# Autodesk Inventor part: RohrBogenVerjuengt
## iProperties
Shininess: 64.0
Length Units: 11269
Angle Units: 11279
Time Units: 11290
Mass Units: 11283
Length Display Precision: 5
Angle Display Precision: 5
Compacted: True
Part Number: RohrBogenVerjuengt
Document SubType Name: Modeling
Created: 2005-01
Material: Standard
Designer: mp
Density: 0.0
Volumn: 0.0
Area: 0.0
PropertySet Name: Model Information
Control State: 0
Master: False
Checked Out: False
Author: mp
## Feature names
1. Sweeping1
2. Wandstärke1
